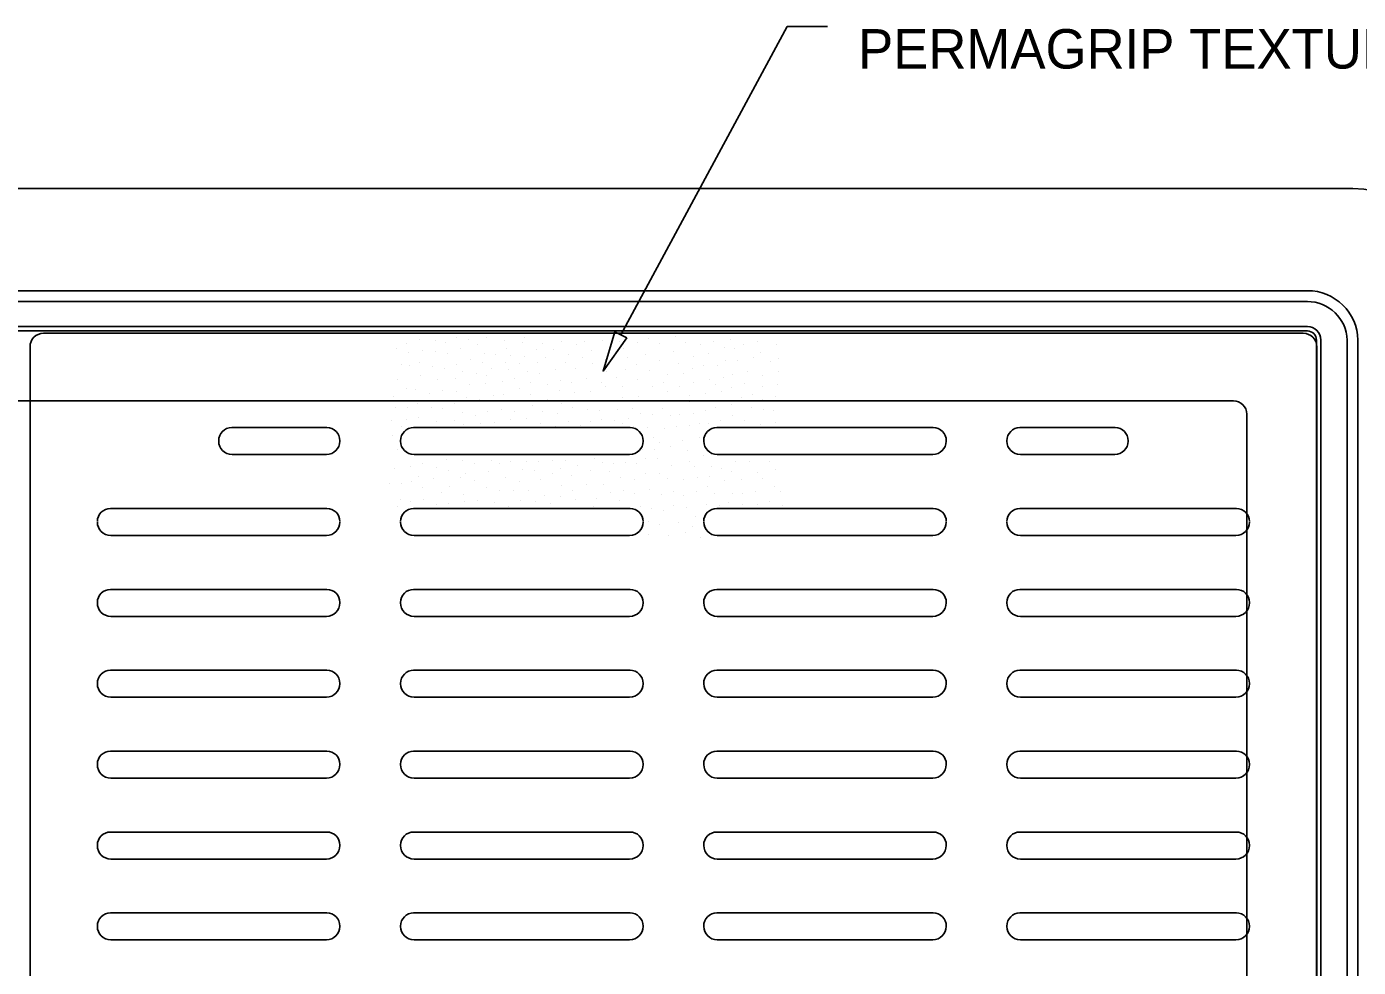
# Model space of a CAD drawing. Extents: x 12.38 to 19.62, y 5.98 to 15.83.
# Drawn here: x 14.982 to 17.009, y 14.236 to 15.667 of the extents above; entities that cross this region are included whole.
import ezdxf

# ---------------------------------------------------------------- set-up
doc = ezdxf.new("R2010")
doc.units = 0
for name, color, linetype in [('Default', 7, 'Continuous'), ('DIMS', 7, 'Continuous'), ('FRAME', 7, 'Continuous'), ('HIDDEN', 7, 'Continuous'), ('TOP', 7, 'Continuous'), ('V7_LEVEL_12', 7, 'Continuous')]:
    doc.layers.add(name, color=color, linetype=linetype)

# ---------------------------------------------------------------- blocks, each defined once
blk = doc.blocks.new('POINT_DISPLAY')
at = {"layer": 'Default'}
blk.add_line((0, 0), (0, 0), dxfattribs=at)

msp = doc.modelspace()

# ---------------------------------------------------------------- linework, layer by layer
at = {"layer": 'DIMS'}
for p, q in [((15.8863, 15.1986), (16.1392, 15.6672)), ((16.1392, 15.6672), (16.2007, 15.6672))]:
    msp.add_line(p, q, dxfattribs=at)
msp.add_lwpolyline([(15.8953, 15.194), (15.8769, 15.2029), (15.8593, 15.1431)], close=True, dxfattribs=at)
at = {"layer": 'FRAME'}
for p, q in [((17.0002, 15.4209), (12.9637, 15.4209)), ((16.931, 15.2655), (13.033, 15.2655)), ((16.931, 15.249), (13.033, 15.249)), ((16.931, 15.211), (13.033, 15.211)), ((16.931, 15.2042), (13.033, 15.2042)), ((16.9447, 13.0356), (16.9447, 15.1905)), ((16.9515, 13.0356), (16.9515, 15.1905)), ((16.9915, 13.0356), (16.9915, 15.1905)), ((17.008, 13.0356), (17.008, 15.1905))]:
    msp.add_line(p, q, dxfattribs=at)
for centre, radius, start, end in [((17.0002, 15.2594), 0.1615, 0, 90), ((16.9312, 15.1887), 0.0768, 1.3125, 90.2197), ((16.9312, 15.1887), 0.0603, 1.6784, 90.279), ((16.931, 15.1905), 0.0205, 0, 90), ((16.931, 15.1905), 0.0137, 0, 90)]:
    msp.add_arc(centre, radius, start, end, dxfattribs=at)
at = {"layer": 'HIDDEN'}
for p, q in [((16.8184, 15.0981), (13.1455, 15.0981)), ((16.8389, 13.1485), (16.8389, 15.0776))]:
    msp.add_line(p, q, dxfattribs=at)
msp.add_arc((16.8184, 15.0776), 0.0205, 0, 90, dxfattribs=at)
at = {"layer": 'TOP'}
for p, q in [((15.9662, 15.2007), (15.0076, 15.2007)), ((15.9662, 15.2007), (16.9248, 15.2007)), ((14.9871, 15.1802), (14.9871, 13.0477)), ((16.9453, 15.1802), (16.9453, 13.0477)), ((15.2941, 15.0572), (15.4388, 15.0572)), ((15.5709, 15.0572), (15.9002, 15.0572)), ((16.3616, 15.0572), (16.0322, 15.0572)), ((16.6384, 15.0572), (16.4936, 15.0572)), ((15.2947, 15.0162), (15.4382, 15.0162)), ((15.5715, 15.0162), (15.8996, 15.0162)), ((16.3609, 15.0162), (16.0329, 15.0162)), ((16.6378, 15.0162), (16.4942, 15.0162)), ((15.1095, 14.9342), (15.4388, 14.9342)), ((15.5709, 14.9342), (15.9002, 14.9342)), ((16.3616, 14.9342), (16.0322, 14.9342)), ((16.8229, 14.9342), (16.4936, 14.9342)), ((15.1101, 14.8931), (15.4382, 14.8931)), ((15.5715, 14.8931), (15.8996, 14.8931)), ((16.3609, 14.8931), (16.0329, 14.8931)), ((16.8223, 14.8931), (16.4942, 14.8931)), ((15.1095, 14.8111), (15.4388, 14.8111)), ((15.5709, 14.8111), (15.9002, 14.8111)), ((16.3616, 14.8111), (16.0322, 14.8111)), ((16.8229, 14.8111), (16.4936, 14.8111)), ((15.1101, 14.7701), (15.4382, 14.7701)), ((15.5715, 14.7701), (15.8996, 14.7701)), ((16.3609, 14.7701), (16.0329, 14.7701)), ((16.8223, 14.7701), (16.4942, 14.7701)), ((15.1095, 14.6881), (15.4388, 14.6881)), ((15.5709, 14.6881), (15.9002, 14.6881)), ((16.3616, 14.6881), (16.0322, 14.6881)), ((16.8229, 14.6881), (16.4936, 14.6881)), ((15.1101, 14.6471), (15.4382, 14.6471)), ((15.5715, 14.6471), (15.8996, 14.6471)), ((16.3609, 14.6471), (16.0329, 14.6471)), ((16.8223, 14.6471), (16.4942, 14.6471)), ((15.1095, 14.5651), (15.4388, 14.5651)), ((15.5709, 14.5651), (15.9002, 14.5651)), ((16.3616, 14.5651), (16.0322, 14.5651)), ((16.8229, 14.5651), (16.4936, 14.5651)), ((15.1101, 14.5241), (15.4382, 14.5241)), ((15.5715, 14.5241), (15.8996, 14.5241)), ((16.3609, 14.5241), (16.0329, 14.5241)), ((16.8223, 14.5241), (16.4942, 14.5241)), ((15.1095, 14.442), (15.4388, 14.442)), ((15.5709, 14.442), (15.9002, 14.442)), ((16.3616, 14.442), (16.0322, 14.442)), ((16.8229, 14.442), (16.4936, 14.442)), ((15.1101, 14.401), (15.4382, 14.401)), ((15.5715, 14.401), (15.8996, 14.401)), ((16.3609, 14.401), (16.0329, 14.401)), ((16.8223, 14.401), (16.4942, 14.401)), ((15.1095, 14.319), (15.4388, 14.319)), ((15.5709, 14.319), (15.9002, 14.319)), ((16.3616, 14.319), (16.0322, 14.319)), ((16.8229, 14.319), (16.4936, 14.319)), ((15.1101, 14.278), (15.4382, 14.278)), ((15.5715, 14.278), (15.8996, 14.278)), ((16.3609, 14.278), (16.0329, 14.278)), ((16.8223, 14.278), (16.4942, 14.278))]:
    msp.add_line(p, q, dxfattribs=at)
for centre, radius, start, end in [((15.0076, 15.1802), 0.0205, 90, 180), ((16.9248, 15.1802), 0.0205, 0, 90), ((15.2941, 15.0373), 0.0199, 90, 180), ((15.4388, 15.0373), 0.0199, 360, 90), ((15.5709, 15.0373), 0.0199, 90, 180), ((15.9002, 15.0373), 0.0199, 360, 90), ((16.0322, 15.0373), 0.0199, 90, 180), ((16.3616, 15.0373), 0.0199, 360, 90), ((16.4936, 15.0373), 0.0199, 90, 180), ((16.6384, 15.0373), 0.0199, 360, 90), ((15.2947, 15.0367), 0.0205, 180, 270), ((15.4382, 15.0367), 0.0205, 270, 0), ((15.5715, 15.0367), 0.0205, 180, 270), ((15.8996, 15.0367), 0.0205, 270, 0), ((16.0329, 15.0367), 0.0205, 180, 270), ((16.3609, 15.0367), 0.0205, 270, 0), ((16.4942, 15.0367), 0.0205, 180, 270), ((16.6378, 15.0367), 0.0205, 270, 0), ((15.1095, 14.9143), 0.0199, 90, 180), ((15.4388, 14.9143), 0.0199, 360, 90), ((15.5709, 14.9143), 0.0199, 90, 180), ((15.9002, 14.9143), 0.0199, 360, 90), ((16.0322, 14.9143), 0.0199, 90, 180), ((16.3616, 14.9143), 0.0199, 360, 90), ((16.4936, 14.9143), 0.0199, 90, 180), ((16.8229, 14.9143), 0.0199, 360, 90), ((15.1101, 14.9136), 0.0205, 180, 270), ((15.4382, 14.9136), 0.0205, 270, 0), ((15.5715, 14.9136), 0.0205, 180, 270), ((15.8996, 14.9136), 0.0205, 270, 0), ((16.0329, 14.9136), 0.0205, 180, 270), ((16.3609, 14.9136), 0.0205, 270, 0), ((16.4942, 14.9136), 0.0205, 180, 270), ((16.8223, 14.9136), 0.0205, 270, 0), ((15.1095, 14.7912), 0.0199, 90, 180), ((15.4388, 14.7912), 0.0199, 360, 90), ((15.5709, 14.7912), 0.0199, 90, 180), ((15.9002, 14.7912), 0.0199, 360, 90), ((16.0322, 14.7912), 0.0199, 90, 180), ((16.3616, 14.7912), 0.0199, 360, 90), ((16.4936, 14.7912), 0.0199, 90, 180), ((16.8229, 14.7912), 0.0199, 360, 90), ((15.1101, 14.7906), 0.0205, 180, 270), ((15.4382, 14.7906), 0.0205, 270, 0), ((15.5715, 14.7906), 0.0205, 180, 270), ((15.8996, 14.7906), 0.0205, 270, 0), ((16.0329, 14.7906), 0.0205, 180, 270), ((16.3609, 14.7906), 0.0205, 270, 0), ((16.4942, 14.7906), 0.0205, 180, 270), ((16.8223, 14.7906), 0.0205, 270, 0), ((15.1095, 14.6682), 0.0199, 90, 180), ((15.4388, 14.6682), 0.0199, 360, 90), ((15.5709, 14.6682), 0.0199, 90, 180), ((15.9002, 14.6682), 0.0199, 360, 90), ((16.0322, 14.6682), 0.0199, 90, 180), ((16.3616, 14.6682), 0.0199, 360, 90), ((16.4936, 14.6682), 0.0199, 90, 180), ((16.8229, 14.6682), 0.0199, 360, 90), ((15.1101, 14.6676), 0.0205, 180, 270), ((15.4382, 14.6676), 0.0205, 270, 0), ((15.5715, 14.6676), 0.0205, 180, 270), ((15.8996, 14.6676), 0.0205, 270, 0), ((16.0329, 14.6676), 0.0205, 180, 270), ((16.3609, 14.6676), 0.0205, 270, 0), ((16.4942, 14.6676), 0.0205, 180, 270), ((16.8223, 14.6676), 0.0205, 270, 0), ((15.1095, 14.5452), 0.0199, 90, 180), ((15.4388, 14.5452), 0.0199, 360, 90), ((15.5709, 14.5452), 0.0199, 90, 180), ((15.9002, 14.5452), 0.0199, 360, 90), ((16.0322, 14.5452), 0.0199, 90, 180), ((16.3616, 14.5452), 0.0199, 360, 90), ((16.4936, 14.5452), 0.0199, 90, 180), ((16.8229, 14.5452), 0.0199, 360, 90), ((15.1101, 14.5446), 0.0205, 180, 270), ((15.4382, 14.5446), 0.0205, 270, 0), ((15.5715, 14.5446), 0.0205, 180, 270), ((15.8996, 14.5446), 0.0205, 270, 0), ((16.0329, 14.5446), 0.0205, 180, 270), ((16.3609, 14.5446), 0.0205, 270, 0), ((16.4942, 14.5446), 0.0205, 180, 270), ((16.8223, 14.5446), 0.0205, 270, 0), ((15.1095, 14.4221), 0.0199, 90, 180), ((15.4388, 14.4221), 0.0199, 360, 90), ((15.5709, 14.4221), 0.0199, 90, 180), ((15.9002, 14.4221), 0.0199, 360, 90), ((16.0322, 14.4221), 0.0199, 90, 180), ((16.3616, 14.4221), 0.0199, 360, 90), ((16.4936, 14.4221), 0.0199, 90, 180), ((16.8229, 14.4221), 0.0199, 360, 90), ((15.1101, 14.4215), 0.0205, 180, 270), ((15.4382, 14.4215), 0.0205, 270, 0), ((15.5715, 14.4215), 0.0205, 180, 270), ((15.8996, 14.4215), 0.0205, 270, 0), ((16.0329, 14.4215), 0.0205, 180, 270), ((16.3609, 14.4215), 0.0205, 270, 0), ((16.4942, 14.4215), 0.0205, 180, 270), ((16.8223, 14.4215), 0.0205, 270, 0), ((15.1095, 14.2991), 0.0199, 90, 180), ((15.4388, 14.2991), 0.0199, 360, 90), ((15.5709, 14.2991), 0.0199, 90, 180), ((15.9002, 14.2991), 0.0199, 360, 90), ((16.0322, 14.2991), 0.0199, 90, 180), ((16.3616, 14.2991), 0.0199, 360, 90), ((16.4936, 14.2991), 0.0199, 90, 180), ((16.8229, 14.2991), 0.0199, 360, 90), ((15.1101, 14.2985), 0.0205, 180, 270), ((15.4382, 14.2985), 0.0205, 270, 0), ((15.5715, 14.2985), 0.0205, 180, 270), ((15.8996, 14.2985), 0.0205, 270, 0), ((16.0329, 14.2985), 0.0205, 180, 270), ((16.3609, 14.2985), 0.0205, 270, 0), ((16.4942, 14.2985), 0.0205, 180, 270), ((16.8223, 14.2985), 0.0205, 270, 0)]:
    msp.add_arc(centre, radius, start, end, dxfattribs=at)

# ---------------------------------------------------------------- block references
at = {"layer": 'TOP', "xscale": 0.008202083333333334, "yscale": 0.008202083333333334}
for p in [(15.5577, 15.1997), (15.5598, 15.1856), (15.5796, 15.1909), (15.6037, 15.1899), (15.6188, 15.1865), (15.6367, 15.1942), (15.6548, 15.192), (15.6675, 15.184), (15.6825, 15.1943), (15.7098, 15.1894), (15.7366, 15.1874), (15.7397, 15.1948), (15.7677, 15.1851), (15.7963, 15.1879), (15.819, 15.1837), (15.8307, 15.1879), (15.8588, 15.1897), (15.8837, 15.1876), (15.9114, 15.1864), (15.9278, 15.193), (15.9443, 15.1855), (15.9693, 15.1957), (15.9853, 15.1874), (16.0069, 15.1844), (16.0278, 15.1887), (16.0535, 15.1908), (16.0729, 15.1844), (16.0937, 15.1888), (16.1233, 15.1833), (15.5446, 15.1778), (15.5635, 15.1708), (15.5851, 15.1745), (15.6037, 15.1725), (15.6225, 15.1705), (15.6418, 15.1769), (15.6574, 15.1615), (15.6788, 15.1699), (15.6953, 15.1684), (15.7129, 15.1773), (15.7176, 15.1667), (15.74, 15.165), (15.7572, 15.1764), (15.771, 15.1633), (15.7839, 15.1755), (15.807, 15.1691), (15.8282, 15.1644), (15.8413, 15.174), (15.8623, 15.1616), (15.8761, 15.1667), (15.8909, 15.1773), (15.8968, 15.1633), (15.9233, 15.1688), (15.945, 15.1598), (15.9662, 15.1729), (15.9966, 15.165), (16.0196, 15.1693), (16.0434, 15.1789), (16.0597, 15.1782), (16.0638, 15.1598), (16.0879, 15.1633), (16.0992, 15.1713), (16.1261, 15.1625), (15.5523, 15.1529), (15.5644, 15.1515), (15.5799, 15.1564), (15.5995, 15.1506), (15.6178, 15.1478), (15.6367, 15.1529), (15.6456, 15.1432), (15.6661, 15.1397), (15.6751, 15.1561), (15.6901, 15.1475), (15.7102, 15.1561), (15.7156, 15.1451), (15.7323, 15.1542), (15.7435, 15.1426), (15.759, 15.157), (15.7631, 15.1399), (15.7865, 15.1456), (15.8024, 15.1561), (15.8175, 15.1478), (15.8434, 15.1547), (15.8647, 15.1427), (15.8938, 15.1455), (15.9103, 15.1533), (15.9295, 15.1443), (15.9743, 15.1547), (15.9813, 15.1395), (15.9954, 15.1465), (16.0117, 15.1515), (16.0328, 15.1512), (16.0449, 15.1589), (16.0565, 15.1387), (16.0784, 15.142), (16.1138, 15.1581), (16.1265, 15.142), (15.5468, 15.1311), (15.5807, 15.1365), (15.6069, 15.1302), (15.634, 15.1313), (15.6561, 15.1234), (15.6797, 15.1242), (15.6825, 15.1367), (15.7059, 15.1272), (15.7249, 15.1321), (15.7487, 15.1253), (15.775, 15.1223), (15.7941, 15.1294), (15.8114, 15.1266), (15.8347, 15.1326), (15.8568, 15.1266), (15.8628, 15.1192), (15.8799, 15.133), (15.8891, 15.1192), (15.9111, 15.1297), (15.9337, 15.1205), (15.9509, 15.1266), (15.9573, 15.1378), (15.9749, 15.1201), (15.9975, 15.1264), (16.0214, 15.1305), (16.0303, 15.1234), (16.0422, 15.134), (16.0751, 15.1245), (16.1014, 15.1365), (16.1025, 15.1191), (16.1244, 15.1234), (15.5395, 15.1045), (15.5607, 15.1174), (15.573, 15.1147), (15.5954, 15.1098), (15.6145, 15.1131), (15.6364, 15.1128), (15.6515, 15.103), (15.6704, 15.0996), (15.6926, 15.106), (15.7074, 15.1082), (15.7318, 15.1172), (15.748, 15.1072), (15.7752, 15.0993), (15.7923, 15.1136), (15.8157, 15.1108), (15.8273, 15.0989), (15.8404, 15.1115), (15.8633, 15.0987), (15.8891, 15.1026), (15.9127, 15.105), (15.9359, 15.0987), (15.9565, 15.1128), (15.9738, 15.0992), (15.9905, 15.1063), (16.0146, 15.1094), (16.0394, 15.1128), (16.0543, 15.118), (16.0698, 15.1036), (16.0861, 15.1081), (16.1014, 15.1005), (16.1222, 15.1048), (15.5435, 15.0884), (15.5621, 15.0873), (15.5773, 15.0934), (15.5978, 15.0873), (15.6152, 15.0863), (15.6324, 15.0944), (15.6458, 15.0801), (15.6827, 15.0818), (15.705, 15.0847), (15.724, 15.0823), (15.726, 15.097), (15.7523, 15.0911), (15.767, 15.0822), (15.7904, 15.0794), (15.7959, 15.0934), (15.8128, 15.0874), (15.8348, 15.0854), (15.8531, 15.0833), (15.8805, 15.0841), (15.9035, 15.087), (15.9161, 15.0788), (15.949, 15.087), (15.9911, 15.0963), (15.9969, 15.0787), (16.0155, 15.084), (16.0303, 15.0873), (16.0543, 15.0928), (16.085, 15.0884), (16.1036, 15.0841), (16.1189, 15.083), (15.5369, 15.0677), (15.5522, 15.0589), (15.5607, 15.0694), (15.5784, 15.073), (15.6053, 15.0659), (15.6327, 15.0685), (15.6474, 15.0621), (15.6651, 15.0756), (15.6723, 15.063), (15.6941, 15.0651), (15.7181, 15.0693), (15.7433, 15.0712), (15.7636, 15.0639), (15.7861, 15.0595), (15.8066, 15.0658), (15.8247, 15.0609), (15.8402, 15.0658), (15.8562, 15.0696), (15.8762, 15.0685), (15.8891, 15.0637), (15.8974, 15.0704), (15.9052, 15.0585), (15.927, 15.058), (15.9337, 15.0774), (15.962, 15.0759), (15.9708, 15.0591), (15.976, 15.0772), (15.9906, 15.0597), (16.0053, 15.0639), (16.0197, 15.0641), (16.0379, 15.0677), (16.0554, 15.0753), (16.074, 15.0677), (16.0992, 15.0622), (16.1211, 15.0644), (15.5386, 15.0455), (15.9361, 15.0418), (15.9533, 15.0552), (15.9795, 15.0378), (16.0054, 15.0421), (15.5457, 15.0239), (15.9195, 15.0235), (15.938, 15.0234), (15.9443, 15.0347), (15.9619, 15.028), (15.9882, 15.023), (15.5654, 14.9988), (15.5851, 15.0021), (15.6207, 15.0085), (15.6458, 15.0072), (15.6641, 15.0027), (15.6895, 15.0078), (15.7019, 15.0031), (15.719, 15.0063), (15.7434, 15.0058), (15.7606, 15.0053), (15.7819, 15.007), (15.8024, 15.0077), (15.8202, 15), (15.8468, 15.0109), (15.8586, 15.0049), (15.8752, 15.0031), (15.894, 15.0039), (15.9096, 15.0023), (15.9232, 15.0095), (15.9427, 15.0105), (15.9635, 14.9999), (15.9912, 15.0063), (15.9986, 14.9977), (16.0117, 15.0141), (16.0237, 14.9975), (16.0609, 15.0053), (16.0817, 15.0053), (16.1123, 15.0053), (15.5424, 14.9955), (15.5783, 14.9828), (15.6011, 14.9791), (15.6057, 14.9961), (15.6233, 14.9922), (15.6419, 14.9813), (15.6493, 14.9874), (15.6844, 14.9898), (15.7113, 14.9815), (15.7359, 14.9934), (15.7544, 14.992), (15.7641, 14.9789), (15.7821, 14.9874), (15.7951, 14.9944), (15.8107, 14.9846), (15.8408, 14.9917), (15.8686, 14.9908), (15.8862, 14.9821), (15.9076, 14.9779), (15.924, 14.9877), (15.9445, 14.9877), (15.957, 14.9791), (15.9821, 14.978), (16.0034, 14.9819), (16.0215, 14.9824), (16.0401, 14.9944), (16.0445, 14.9769), (16.0543, 14.9911), (16.0697, 14.978), (16.0937, 14.9889), (16.1025, 14.9791), (16.1222, 14.9933), (15.5347, 14.9725), (15.5524, 14.9717), (15.5675, 14.9747), (15.5838, 14.9662), (15.6135, 14.9583), (15.6262, 14.9671), (15.6636, 14.9765), (15.682, 14.9656), (15.7019, 14.9616), (15.7235, 14.961), (15.7323, 14.9745), (15.7463, 14.9616), (15.7962, 14.9693), (15.8125, 14.9616), (15.8334, 14.97), (15.86, 14.9703), (15.8706, 14.9588), (15.89, 14.9616), (15.9074, 14.9564), (15.9292, 14.9627), (15.9668, 14.9605), (16.0007, 14.9605), (16.0182, 14.9671), (16.0292, 14.9572), (16.0565, 14.9572), (16.0717, 14.957), (16.0915, 14.9605), (16.12, 14.9682), (16.1298, 14.9607), (15.546, 14.9367), (15.5511, 14.9485), (15.5654, 14.9452), (15.5861, 14.9474), (15.605, 14.9404), (15.6244, 14.9419), (15.6474, 14.9561), (15.6485, 14.9441), (15.6683, 14.9458), (15.6942, 14.9439), (15.7145, 14.9377), (15.7341, 14.9468), (15.7568, 14.9445), (15.7706, 14.954), (15.7793, 14.9422), (15.794, 14.9518), (15.817, 14.9474), (15.8439, 14.9367), (15.8495, 14.9493), (15.8845, 14.9467), (15.9158, 14.9376), (15.9482, 14.9561), (15.9656, 14.9395), (15.9822, 14.9542), (16.0161, 14.9408), (16.0357, 14.9386), (16.0505, 14.9432), (16.0718, 14.9408), (16.0948, 14.9397), (16.1123, 14.9452), (16.1316, 14.9395), (15.9325, 14.9337), (15.9515, 14.931), (15.9865, 14.9354), (15.9996, 14.9222), (16.0959, 14.9354), (15.9287, 14.9137), (15.9451, 14.9097), (15.9734, 14.9124), (15.9843, 14.8971), (15.9951, 14.9072), (15.9278, 14.8951), (15.9592, 14.8927), (16.0073, 14.8894)]:
    msp.add_blockref('POINT_DISPLAY', p, dxfattribs=at)

# ---------------------------------------------------------------- texts
at = {"layer": 'V7_LEVEL_12'}
msp.add_text('PERMAGRIP TEXTURE', height=0.06, dxfattribs=at).set_placement((16.2472, 15.6034))

doc.saveas('drawing.dxf')
